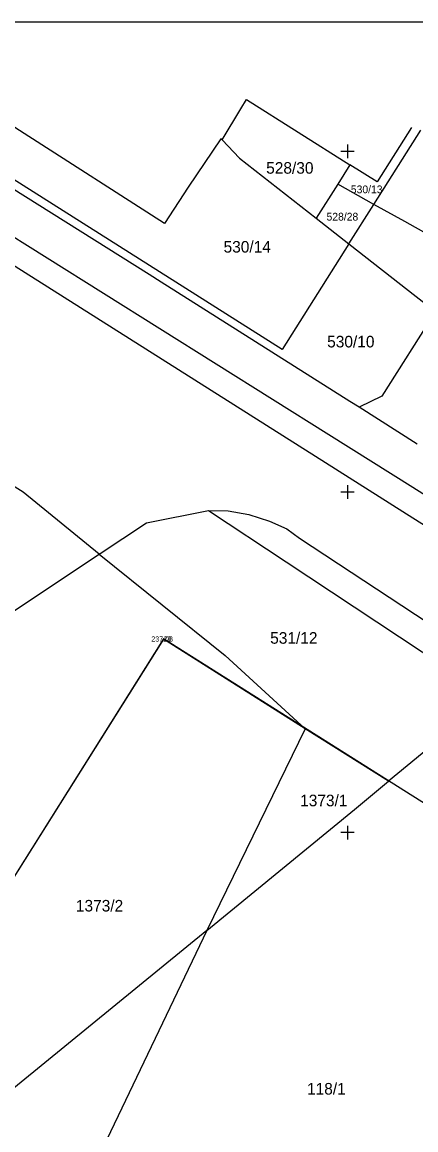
# Model space of a CAD drawing. Extents: x -645398 to -644998, y -1063322 to -1063031.
# Drawn here: x -645197.8 to -645140, y -1063193.6 to -1063031 of the extents above; entities that cross this region are included whole.
import ezdxf

# ---------------------------------------------------------------- set-up
doc = ezdxf.new("R2010")
doc.units = 0
for name, color, linetype in [('Bod', 7, 'Continuous'), ('Hranice KN pozemků', 7, 'Continuous'), ('Rámeček', 7, 'Continuous'), ('Souřadnicové křížky', 7, 'Continuous'), ('Stavby', 7, 'Continuous'), ('Vnitřní kresba parcel', 7, 'Continuous'), ('Výška', 7, 'Continuous'), ('Čísla parcel', 7, 'Continuous'), ('Čísla stavebních parcel', 7, 'Continuous'), ('Číslo bodu', 7, 'Continuous')]:
    doc.layers.add(name, color=color, linetype=linetype)

msp = doc.modelspace()

# ---------------------------------------------------------------- linework, layer by layer
at = {"layer": 'Bod'}
for q in [(-645177.1, -1063121.52), (-645177.1, -1063121.62), (-645177, -1063121.52), (-645177, -1063121.62)]:
    msp.add_line((-645177.05, -1063121.57), q, dxfattribs=at)
at = {"layer": 'Hranice KN pozemků'}
for p, q in [((-645146.11, -1063057.77), (-645139.21, -1063046.87)), ((-645149.65, -1063051.95), (-645151.44, -1063054.79)), ((-645151.44, -1063054.79), (-645154.6, -1063059.81)), ((-645146.11, -1063057.77), (-645151.44, -1063054.79)), ((-645149.78, -1063063.57), (-645146.11, -1063057.77)), ((-645154.6, -1063059.81), (-645149.78, -1063063.57)), ((-645139.74, -1063092.95), (-645148.3, -1063087.54)), ((-645213.42, -1063127.02), (-645186.47, -1063109.12)), ((-645177.04, -1063121.61), (-645236.42, -1063215.87)), ((-645156.21, -1063134.74), (-645177.04, -1063121.61)), ((-645129.04, -1063130.08), (-645143.96, -1063142.46)), ((-645156.21, -1063134.74), (-645170.69, -1063164.36)), ((-645143.96, -1063142.46), (-645156.21, -1063134.74)), ((-645148.96, -1063146.61), (-645143.96, -1063142.46)), ((-645170.69, -1063164.36), (-645148.96, -1063146.61)), ((-645170.69, -1063164.36), (-645221.27, -1063205.67)), ((-645170.69, -1063164.36), (-645199.14, -1063223.84))]:
    msp.add_line(p, q, dxfattribs=at)
for points in [[(-645236.73, -1063042.91), (-645233.9, -1063041.56), (-645230.85, -1063042.43), (-645219.03, -1063050.07), (-645152.72, -1063091.57), (-645140.39, -1063099.29), (-645051.35, -1063155.61)], [(-645236.73, -1063042.91), (-645154.72, -1063094.74), (-645140.39, -1063103.8), (-645055.15, -1063157.46)], [(-645168.41, -1063048.3), (-645165.65, -1063043.73), (-645164.84, -1063042.4), (-645149.65, -1063051.95)], [(-645168.41, -1063048.3), (-645168.62, -1063048.16), (-645173.43, -1063055.26), (-645176.87, -1063060.58), (-645197.51, -1063047.38), (-645199.73, -1063045.93), (-645202.8, -1063044.04)], [(-645140.61, -1063046.51), (-645145.66, -1063054.46), (-645149.65, -1063051.95)], [(-645168.41, -1063048.3), (-645165.86, -1063051.01), (-645154.6, -1063059.81)], [(-645149.78, -1063063.57), (-645159.6, -1063079.08), (-645204.52, -1063050.69)], [(-645148.3, -1063087.54), (-645149.64, -1063086.69), (-645177.4, -1063069.18), (-645179.16, -1063068.05), (-645201.56, -1063054.02), (-645203.84, -1063052.54)], [(-645125.1, -1063054.47), (-645132.12, -1063065.61), (-645135.23, -1063063.87), (-645141.6, -1063060.3), (-645146.11, -1063057.77)], [(-645149.78, -1063063.57), (-645139.91, -1063071.29), (-645137.09, -1063073.49), (-645144.94, -1063085.95), (-645148.3, -1063087.54)], [(-645186.47, -1063109.12), (-645197.66, -1063100.03), (-645232, -1063078.56), (-645252.67, -1063067.66)], [(-645186.47, -1063109.12), (-645179.53, -1063104.51), (-645170.44, -1063102.69), (-645159.02, -1063110.24), (-645129.04, -1063130.08)], [(-645186.47, -1063109.12), (-645167.98, -1063124.02), (-645156.21, -1063134.74)]]:
    msp.add_lwpolyline(points, dxfattribs=at)
at = {"layer": 'Rámeček'}
msp.add_line((-644998.25, -1063031.02), (-645398.25, -1063031.02), dxfattribs=at)
at = {"layer": 'Souřadnicové křížky'}
for p, q in [((-645149, -1063050), (-645151, -1063050)), ((-645150, -1063049), (-645150, -1063051)), ((-645150, -1063099), (-645150, -1063101)), ((-645149, -1063100), (-645151, -1063100)), ((-645150, -1063149), (-645150, -1063151)), ((-645149, -1063150), (-645151, -1063150))]:
    msp.add_line(p, q, dxfattribs=at)
at = {"layer": 'Stavby'}
for p, q in [((-645177.05, -1063121.57), (-645201.53, -1063160.47)), ((-645106.24, -1063166.23), (-645177.05, -1063121.57))]:
    msp.add_line(p, q, dxfattribs=at)
at = {"layer": 'Vnitřní kresba parcel'}
for p, q in [((-645170.44, -1063102.69), (-645167.51, -1063102.76)), ((-645167.51, -1063102.76), (-645164.48, -1063103.32)), ((-645164.48, -1063103.32), (-645161.46, -1063104.3)), ((-645161.46, -1063104.3), (-645158.89, -1063105.42)), ((-645158.89, -1063105.42), (-645157.06, -1063106.79)), ((-645157.06, -1063106.79), (-645125.74, -1063127.34))]:
    msp.add_line(p, q, dxfattribs=at)

# ---------------------------------------------------------------- texts
at = {"layer": 'Výška'}
msp.add_text('237.08', height=0.75, dxfattribs=at).set_placement((-645178.82, -1063121.95))
at = {"layer": 'Čísla parcel'}
for s, height, p in [('528/30', 1.7, (-645161.95, -1063053.27)), ('530/13', 1.139, (-645149.51, -1063056.14)), ('528/28', 1.139, (-645153.08, -1063060.15)), ('530/14', 1.7, (-645168.21, -1063064.85)), ('530/10', 1.7, (-645152.99, -1063078.77)), ('531/12', 1.7, (-645161.36, -1063122.27))]:
    msp.add_text(s, height=height, dxfattribs=at).set_placement(p)
at = {"layer": 'Čísla stavebních parcel'}
for s, p in [('1373/1', (-645156.96, -1063146.13)), ('1373/2', (-645189.91, -1063161.58)), ('118/1', (-645155.95, -1063188.45))]:
    msp.add_text(s, height=1.7, dxfattribs=at).set_placement(p)
at = {"layer": 'Číslo bodu'}
msp.add_text('28', height=0.75, dxfattribs=at).set_placement((-645177.05, -1063121.95))

doc.saveas('drawing.dxf')
